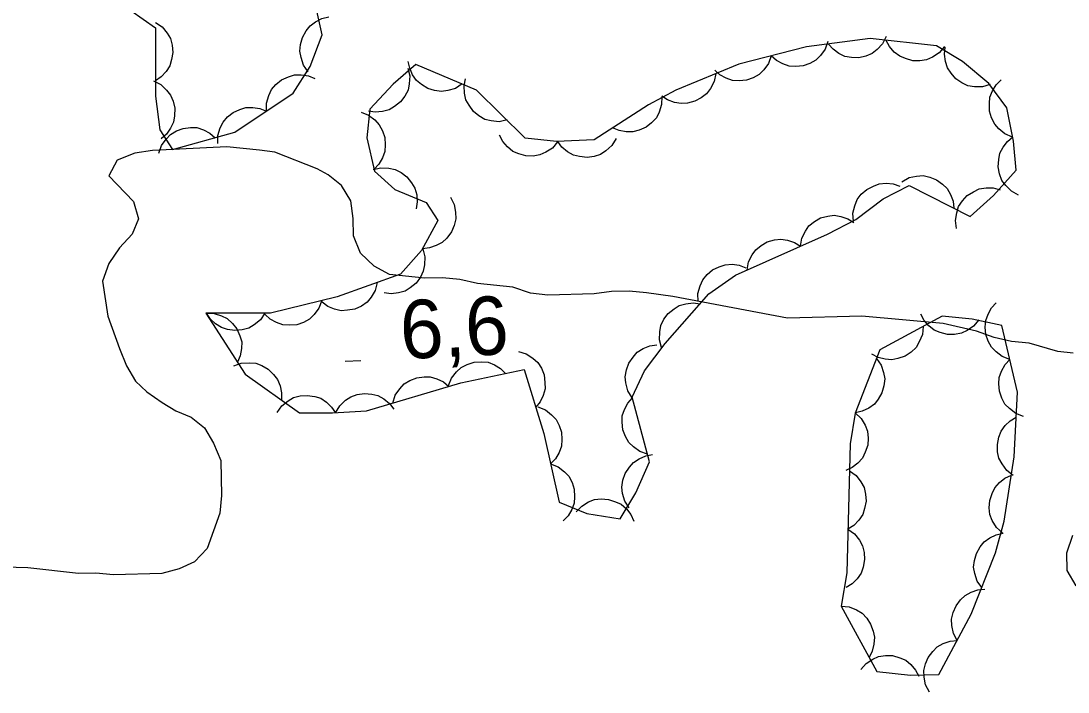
# Model space of a CAD drawing. Extents: x 336540 to 340074, y 5572036 to 5573747.
# Drawn here: x 337134.4 to 337188.2, y 5572878.8 to 5572913.2 of the extents above; entities that cross this region are included whole.
import ezdxf

# ---------------------------------------------------------------- set-up
doc = ezdxf.new("R2010")
doc.units = 0
for name, color, linetype in [('Niveau 2', 7, 'Continuous'), ('Niveau 3', 7, 'Continuous'), ('Niveau 44', 7, 'Continuous')]:
    doc.layers.add(name, color=color, linetype=linetype)

msp = doc.modelspace()

# ---------------------------------------------------------------- linework, layer by layer
at = {"layer": 'Niveau 2'}
for points in [[(337150.88, 5572904.79), (337150.19, 5572905.34), (337149.62, 5572905.66), (337147.46, 5572906.51), (337146.67, 5572906.61), (337144.98, 5572906.79), (337141.16, 5572906.59), (337140.26, 5572906.46), (337139.36, 5572906.1), (337138.93, 5572905.3), (337140.2, 5572903.98), (337140.45, 5572903.09), (337140.13, 5572902.29), (337139.47, 5572901.6), (337138.92, 5572900.8), (337138.6, 5572899.89), (337138.87, 5572898.09), (337139.47, 5572896.42), (337139.83, 5572895.53), (337140.3, 5572894.75), (337140.87, 5572894.2), (337141.67, 5572893.65), (337142.36, 5572893.22), (337143.15, 5572892.9), (337143.84, 5572892.35), (337144.31, 5572891.57), (337144.67, 5572890.68), (337144.71, 5572888.88), (337144.62, 5572887.98), (337143.98, 5572886.16), (337143.32, 5572885.47), (337142.54, 5572885.11), (337141.64, 5572884.87), (337139.17, 5572884.81), (337138.26, 5572884.9), (337137.36, 5572884.88), (337134.77, 5572885.16), (337130.6, 5572885.29)], [(337188.47, 5572896.19), (337187.68, 5572896.28), (337186.2, 5572896.7), (337185.3, 5572896.79), (337184.4, 5572896.99), (337183.49, 5572897.31), (337181.79, 5572897.72), (337177.61, 5572898.08), (337173.79, 5572897.99), (337167.9, 5572899.1), (337166.55, 5572899.29), (337165.65, 5572899.38), (337164.74, 5572899.36), (337163.85, 5572899.23), (337161.48, 5572899.17), (337160.58, 5572899.27), (337159.67, 5572899.58), (337157.87, 5572899.77), (337156.96, 5572899.97), (337156.06, 5572900.06), (337155.16, 5572900.04), (337153.35, 5572900.23), (337152.55, 5572900.66), (337151.86, 5572901.32), (337151.5, 5572902.21), (337151.48, 5572903.11), (337151.35, 5572904.01), (337150.88, 5572904.79)], [(337188.62, 5572884.25), (337188.16, 5572885.03), (337188.14, 5572885.93), (337188.45, 5572886.84)]]:
    msp.add_lwpolyline(points, dxfattribs=at)
at = {"layer": 'Niveau 3'}
msp.add_line((337151.07, 5572895.78), (337151.87, 5572895.82), dxfattribs=at)
at = {"layer": 'Niveau 44'}
for points in [[(337138.45, 5572914.43), (337140.05, 5572913.79), (337141.32, 5572912.9), (337141.32, 5572909.39), (337141.55, 5572907.66), (337142.2, 5572906.65), (337145.4, 5572907.53), (337148.4, 5572909.54), (337149.27, 5572910.9), (337149.88, 5572912.54), (337149.54, 5572914.07), (337148.69, 5572915.61), (337147.65, 5572916.8), (337144.62, 5572918.57), (337141.35, 5572917.79), (337139.97, 5572916.95), (337138.53, 5572915.98), (337138.45, 5572914.43)], [(337141.32, 5572913.17), (337141.67, 5572912.94), (337141.92, 5572912.62), (337142.09, 5572912.34), (337142.18, 5572912), (337142.22, 5572911.63), (337142.15, 5572911.26), (337142.06, 5572910.94), (337141.87, 5572910.65), (337141.62, 5572910.38), (337141.32, 5572910.17)], [(337149.17, 5572910.64), (337148.93, 5572910.98), (337148.8, 5572911.37), (337148.74, 5572911.69), (337148.77, 5572912.04), (337148.87, 5572912.4), (337149.06, 5572912.73), (337149.26, 5572912.99), (337149.54, 5572913.2), (337149.87, 5572913.37), (337150.22, 5572913.45)], [(337178.86, 5572912.45), (337178.67, 5572912.07), (337178.39, 5572911.78), (337178.14, 5572911.57), (337177.81, 5572911.44), (337177.45, 5572911.36), (337177.07, 5572911.37), (337176.74, 5572911.42), (337176.43, 5572911.57), (337176.13, 5572911.79), (337175.89, 5572912.06)], [(337143.91, 5572898.24), (337145.93, 5572895.11), (337148.72, 5572893.13), (337150.41, 5572893.12), (337152.16, 5572893.23), (337157.01, 5572894.66), (337160.26, 5572895.35), (337161.27, 5572892.07), (337162.06, 5572888.54), (337163.48, 5572887.95), (337165.2, 5572887.68), (337165.99, 5572889.01), (337166.7, 5572890.61), (337165.81, 5572893.93), (337166.45, 5572895.29), (337167.5, 5572896.69), (337169.75, 5572899.23), (337171.11, 5572900.19), (337175.84, 5572902.3), (337177.3, 5572903.05), (337178.7, 5572904.11), (337180.04, 5572904.8), (337183.17, 5572903.21), (337184.37, 5572904.28), (337185.53, 5572905.59), (337185.39, 5572907.07), (337185.05, 5572908.79), (337184.13, 5572910.04), (337182.78, 5572911.16), (337181.45, 5572911.97), (337178.04, 5572912.34), (337174.76, 5572911.91), (337171.29, 5572911.03), (337168.06, 5572909.69), (337166.64, 5572908.93), (337163.85, 5572907.15), (337161.92, 5572907.05), (337160.31, 5572907.23), (337157.82, 5572909.7), (337154.7, 5572911.01), (337153.53, 5572910), (337152.34, 5572908.71), (337152.18, 5572907.25), (337152.57, 5572905.54), (337153.61, 5572904.6), (337155.23, 5572903.92), (337155.82, 5572903), (337154.98, 5572901.46), (337153.91, 5572900.24), (337150.65, 5572899.08), (337147.23, 5572898.25), (337143.91, 5572898.24)], [(337175.86, 5572912.19), (337175.72, 5572911.8), (337175.48, 5572911.47), (337175.24, 5572911.23), (337174.94, 5572911.06), (337174.59, 5572910.94), (337174.21, 5572910.91), (337173.88, 5572910.92), (337173.55, 5572911.04), (337173.22, 5572911.21), (337172.95, 5572911.45)], [(337181.85, 5572911.93), (337181.58, 5572911.61), (337181.23, 5572911.39), (337180.93, 5572911.25), (337180.59, 5572911.19), (337180.22, 5572911.2), (337179.85, 5572911.31), (337179.55, 5572911.43), (337179.27, 5572911.65), (337179.03, 5572911.93), (337178.86, 5572912.25)], [(337184.2, 5572909.98), (337183.8, 5572909.87), (337183.39, 5572909.87), (337183.06, 5572909.92), (337182.74, 5572910.07), (337182.44, 5572910.28), (337182.19, 5572910.57), (337182, 5572910.84), (337181.9, 5572911.17), (337181.85, 5572911.54), (337181.89, 5572911.9)], [(337172.95, 5572911.45), (337172.81, 5572911.06), (337172.57, 5572910.73), (337172.34, 5572910.5), (337172.03, 5572910.33), (337171.68, 5572910.2), (337171.3, 5572910.17), (337170.97, 5572910.18), (337170.64, 5572910.3), (337170.31, 5572910.48), (337170.05, 5572910.71)], [(337154.29, 5572910.82), (337154.39, 5572910.42), (337154.36, 5572910.01), (337154.3, 5572909.69), (337154.13, 5572909.38), (337153.91, 5572909.09), (337153.6, 5572908.85), (337153.32, 5572908.68), (337152.98, 5572908.6), (337152.61, 5572908.57), (337152.26, 5572908.62)], [(337157.08, 5572910.01), (337156.73, 5572909.78), (337156.34, 5572909.67), (337156.01, 5572909.62), (337155.66, 5572909.67), (337155.31, 5572909.78), (337154.99, 5572909.99), (337154.73, 5572910.19), (337154.53, 5572910.48), (337154.38, 5572910.82), (337154.31, 5572911.17)], [(337147.02, 5572908.62), (337147.02, 5572909.03), (337147.14, 5572909.42), (337147.28, 5572909.72), (337147.51, 5572909.99), (337147.8, 5572910.22), (337148.15, 5572910.37), (337148.46, 5572910.48), (337148.81, 5572910.48), (337149.18, 5572910.42), (337149.51, 5572910.29)], [(337159.38, 5572908.16), (337158.97, 5572908.07), (337158.56, 5572908.12), (337158.24, 5572908.19), (337157.94, 5572908.37), (337157.65, 5572908.6), (337157.43, 5572908.92), (337157.27, 5572909.2), (337157.2, 5572909.54), (337157.18, 5572909.91), (337157.25, 5572910.27)], [(337170.1, 5572910.54), (337170.02, 5572910.13), (337169.83, 5572909.77), (337169.63, 5572909.5), (337169.35, 5572909.29), (337169.02, 5572909.12), (337168.65, 5572909.03), (337168.33, 5572909), (337167.98, 5572909.06), (337167.63, 5572909.19), (337167.33, 5572909.39)], [(337141.22, 5572910.17), (337141.59, 5572909.98), (337141.89, 5572909.7), (337142.09, 5572909.44), (337142.23, 5572909.12), (337142.31, 5572908.76), (337142.29, 5572908.38), (337142.25, 5572908.05), (337142.09, 5572907.74), (337141.88, 5572907.43), (337141.61, 5572907.19)], [(337185.35, 5572907.28), (337184.96, 5572907.45), (337184.65, 5572907.71), (337184.43, 5572907.95), (337184.27, 5572908.27), (337184.17, 5572908.62), (337184.16, 5572909), (337184.18, 5572909.33), (337184.32, 5572909.66), (337184.51, 5572909.97), (337184.77, 5572910.23)], [(337167.33, 5572909.37), (337167.32, 5572908.96), (337167.19, 5572908.57), (337167.05, 5572908.27), (337166.81, 5572908.01), (337166.52, 5572907.79), (337166.16, 5572907.64), (337165.85, 5572907.55), (337165.5, 5572907.55), (337165.14, 5572907.62), (337164.8, 5572907.76)], [(337144.53, 5572906.95), (337144.53, 5572907.36), (337144.65, 5572907.75), (337144.79, 5572908.05), (337145.02, 5572908.32), (337145.31, 5572908.55), (337145.66, 5572908.7), (337145.97, 5572908.81), (337146.32, 5572908.81), (337146.69, 5572908.75), (337147.02, 5572908.62)], [(337151.88, 5572908.56), (337152.27, 5572908.41), (337152.59, 5572908.16), (337152.82, 5572907.92), (337152.98, 5572907.61), (337153.1, 5572907.26), (337153.12, 5572906.88), (337153.1, 5572906.55), (337152.98, 5572906.22), (337152.79, 5572905.9), (337152.55, 5572905.64)], [(337141.5, 5572906.46), (337141.63, 5572906.85), (337141.87, 5572907.18), (337142.09, 5572907.42), (337142.4, 5572907.6), (337142.74, 5572907.73), (337143.12, 5572907.77), (337143.45, 5572907.77), (337143.79, 5572907.66), (337144.11, 5572907.49), (337144.39, 5572907.25)], [(337161.98, 5572907.04), (337161.71, 5572906.72), (337161.37, 5572906.51), (337161.07, 5572906.37), (337160.72, 5572906.31), (337160.35, 5572906.32), (337159.99, 5572906.43), (337159.68, 5572906.55), (337159.41, 5572906.78), (337159.17, 5572907.06), (337159, 5572907.38)], [(337164.98, 5572907.21), (337164.77, 5572906.85), (337164.46, 5572906.58), (337164.19, 5572906.39), (337163.86, 5572906.29), (337163.49, 5572906.23), (337163.11, 5572906.28), (337162.79, 5572906.35), (337162.49, 5572906.53), (337162.2, 5572906.77), (337161.99, 5572907.05)], [(337185.65, 5572904.3), (337185.29, 5572904.5), (337185, 5572904.79), (337184.8, 5572905.06), (337184.68, 5572905.39), (337184.61, 5572905.75), (337184.64, 5572906.13), (337184.7, 5572906.45), (337184.87, 5572906.76), (337185.09, 5572907.06), (337185.37, 5572907.29)], [(337152.5, 5572905.61), (337152.9, 5572905.71), (337153.31, 5572905.68), (337153.63, 5572905.62), (337153.94, 5572905.46), (337154.24, 5572905.24), (337154.48, 5572904.94), (337154.65, 5572904.66), (337154.74, 5572904.32), (337154.77, 5572903.95), (337154.72, 5572903.6)], [(337177.17, 5572902.95), (337177.15, 5572903.37), (337177.25, 5572903.76), (337177.37, 5572904.07), (337177.58, 5572904.35), (337177.86, 5572904.6), (337178.2, 5572904.77), (337178.5, 5572904.89), (337178.85, 5572904.91), (337179.22, 5572904.88), (337179.56, 5572904.76)], [(337179.66, 5572904.99), (337180.03, 5572905.2), (337180.42, 5572905.28), (337180.75, 5572905.31), (337181.1, 5572905.23), (337181.44, 5572905.09), (337181.75, 5572904.87), (337181.99, 5572904.65), (337182.16, 5572904.34), (337182.29, 5572903.99), (337182.33, 5572903.63)], [(337182.47, 5572902.59), (337182.42, 5572903), (337182.48, 5572903.4), (337182.58, 5572903.72), (337182.77, 5572904.01), (337183.02, 5572904.28), (337183.35, 5572904.48), (337183.64, 5572904.63), (337183.99, 5572904.68), (337184.36, 5572904.67), (337184.71, 5572904.58)], [(337156.47, 5572904.19), (337156.66, 5572903.82), (337156.73, 5572903.42), (337156.75, 5572903.09), (337156.66, 5572902.74), (337156.52, 5572902.41), (337156.28, 5572902.1), (337156.05, 5572901.87), (337155.74, 5572901.71), (337155.39, 5572901.59), (337155.03, 5572901.55)], [(337174.45, 5572901.68), (337174.52, 5572902.09), (337174.71, 5572902.45), (337174.89, 5572902.73), (337175.17, 5572902.95), (337175.49, 5572903.13), (337175.86, 5572903.22), (337176.19, 5572903.27), (337176.53, 5572903.21), (337176.88, 5572903.09), (337177.19, 5572902.9)], [(337171.71, 5572900.46), (337171.78, 5572900.87), (337171.97, 5572901.23), (337172.16, 5572901.5), (337172.43, 5572901.72), (337172.75, 5572901.9), (337173.12, 5572902), (337173.45, 5572902.05), (337173.79, 5572901.99), (337174.14, 5572901.87), (337174.45, 5572901.68)], [(337155.05, 5572901.54), (337155.16, 5572901.14), (337155.14, 5572900.73), (337155.08, 5572900.4), (337154.93, 5572900.09), (337154.71, 5572899.79), (337154.41, 5572899.55), (337154.14, 5572899.37), (337153.8, 5572899.28), (337153.43, 5572899.24), (337153.07, 5572899.28)], [(337169.2, 5572898.84), (337169.19, 5572899.26), (337169.3, 5572899.65), (337169.43, 5572899.95), (337169.66, 5572900.22), (337169.94, 5572900.46), (337170.28, 5572900.62), (337170.59, 5572900.73), (337170.94, 5572900.75), (337171.31, 5572900.7), (337171.65, 5572900.57)], [(337152.71, 5572899.81), (337152.61, 5572899.41), (337152.4, 5572899.06), (337152.19, 5572898.81), (337151.9, 5572898.61), (337151.56, 5572898.45), (337151.18, 5572898.39), (337150.86, 5572898.36), (337150.52, 5572898.45), (337150.18, 5572898.59), (337149.89, 5572898.81)], [(337149.86, 5572898.89), (337149.72, 5572898.5), (337149.47, 5572898.17), (337149.24, 5572897.94), (337148.93, 5572897.77), (337148.58, 5572897.65), (337148.19, 5572897.63), (337147.87, 5572897.64), (337147.54, 5572897.76), (337147.21, 5572897.94), (337146.95, 5572898.18)], [(337167.31, 5572896.48), (337167.21, 5572896.88), (337167.23, 5572897.29), (337167.28, 5572897.61), (337167.44, 5572897.93), (337167.66, 5572898.22), (337167.96, 5572898.46), (337168.23, 5572898.64), (337168.57, 5572898.73), (337168.94, 5572898.77), (337169.3, 5572898.72)], [(337185.21, 5572895.86), (337184.82, 5572896.01), (337184.5, 5572896.26), (337184.26, 5572896.49), (337184.1, 5572896.8), (337183.98, 5572897.15), (337183.95, 5572897.53), (337183.97, 5572897.86), (337184.09, 5572898.19), (337184.27, 5572898.51), (337184.51, 5572898.78)], [(337143.91, 5572898.24), (337144.33, 5572898.23), (337144.71, 5572898.1), (337145.01, 5572897.96), (337145.27, 5572897.72), (337145.5, 5572897.43), (337145.65, 5572897.08), (337145.75, 5572896.77), (337145.74, 5572896.42), (337145.68, 5572896.05), (337145.54, 5572895.72)], [(337146.94, 5572898.25), (337146.71, 5572897.9), (337146.39, 5572897.65), (337146.11, 5572897.47), (337145.77, 5572897.38), (337145.4, 5572897.35), (337145.02, 5572897.41), (337144.71, 5572897.5), (337144.41, 5572897.69), (337144.14, 5572897.94), (337143.94, 5572898.24)], [(337176.54, 5572883.2), (337178.37, 5572879.85), (337180.11, 5572879.65), (337181.56, 5572879.69), (337183.23, 5572882.78), (337184.47, 5572885.94), (337184.92, 5572887.57), (337185.43, 5572890.86), (337185.61, 5572894.19), (337184.79, 5572897.61), (337183.27, 5572897.93), (337181.73, 5572898.08), (337178.53, 5572896.36), (337177.27, 5572893.1), (337177.01, 5572891.53), (337176.83, 5572884.91), (337176.54, 5572883.2)], [(337183.62, 5572897.9), (337183.35, 5572897.57), (337183.01, 5572897.35), (337182.72, 5572897.21), (337182.37, 5572897.15), (337182, 5572897.15), (337181.63, 5572897.25), (337181.33, 5572897.37), (337181.05, 5572897.59), (337180.81, 5572897.87), (337180.63, 5572898.19)], [(337180.76, 5572897.56), (337180.72, 5572897.14), (337180.56, 5572896.77), (337180.39, 5572896.48), (337180.14, 5572896.24), (337179.83, 5572896.04), (337179.46, 5572895.92), (337179.15, 5572895.85), (337178.8, 5572895.88), (337178.44, 5572895.97), (337178.12, 5572896.14)], [(337159.97, 5572896.28), (337160.37, 5572896.15), (337160.71, 5572895.93), (337160.96, 5572895.71), (337161.15, 5572895.41), (337161.28, 5572895.07), (337161.33, 5572894.69), (337161.34, 5572894.36), (337161.24, 5572894.02), (337161.08, 5572893.69), (337160.86, 5572893.41)], [(337165.8, 5572893.9), (337165.58, 5572894.26), (337165.49, 5572894.66), (337165.45, 5572894.98), (337165.51, 5572895.33), (337165.64, 5572895.68), (337165.86, 5572895.99), (337166.07, 5572896.24), (337166.37, 5572896.42), (337166.72, 5572896.56), (337167.07, 5572896.62)], [(337156.38, 5572894.53), (337156.53, 5572894.91), (337156.79, 5572895.23), (337157.03, 5572895.46), (337157.34, 5572895.61), (337157.7, 5572895.72), (337158.08, 5572895.74), (337158.41, 5572895.72), (337158.73, 5572895.59), (337159.05, 5572895.4), (337159.31, 5572895.15)], [(337178.36, 5572895.92), (337178.6, 5572895.58), (337178.72, 5572895.19), (337178.78, 5572894.87), (337178.74, 5572894.52), (337178.64, 5572894.16), (337178.45, 5572893.83), (337178.25, 5572893.57), (337177.96, 5572893.37), (337177.63, 5572893.21), (337177.28, 5572893.13)], [(337185.91, 5572892.94), (337185.52, 5572893.09), (337185.2, 5572893.34), (337184.96, 5572893.57), (337184.8, 5572893.88), (337184.68, 5572894.23), (337184.65, 5572894.62), (337184.66, 5572894.94), (337184.78, 5572895.27), (337184.97, 5572895.6), (337185.21, 5572895.86)], [(337145.34, 5572895.53), (337145.73, 5572895.68), (337146.14, 5572895.7), (337146.47, 5572895.68), (337146.79, 5572895.56), (337147.11, 5572895.37), (337147.38, 5572895.1), (337147.59, 5572894.84), (337147.72, 5572894.52), (337147.79, 5572894.15), (337147.79, 5572893.79)], [(337153.51, 5572893.63), (337153.64, 5572894.03), (337153.87, 5572894.36), (337154.09, 5572894.61), (337154.39, 5572894.79), (337154.74, 5572894.92), (337155.12, 5572894.97), (337155.44, 5572894.97), (337155.78, 5572894.87), (337156.11, 5572894.71), (337156.39, 5572894.48)], [(337147.57, 5572893.14), (337147.81, 5572893.48), (337148.13, 5572893.74), (337148.41, 5572893.91), (337148.75, 5572893.99), (337149.12, 5572894.02), (337149.5, 5572893.96), (337149.81, 5572893.87), (337150.1, 5572893.67), (337150.37, 5572893.42), (337150.57, 5572893.12)], [(337150.57, 5572893.13), (337150.79, 5572893.49), (337151.08, 5572893.77), (337151.36, 5572893.95), (337151.69, 5572894.07), (337152.05, 5572894.12), (337152.44, 5572894.08), (337152.75, 5572894.01), (337153.06, 5572893.84), (337153.35, 5572893.6), (337153.57, 5572893.32)], [(337166.59, 5572891), (337166.2, 5572891.14), (337165.87, 5572891.38), (337165.63, 5572891.61), (337165.46, 5572891.91), (337165.33, 5572892.26), (337165.29, 5572892.64), (337165.3, 5572892.97), (337165.41, 5572893.3), (337165.58, 5572893.63), (337165.82, 5572893.9)], [(337160.96, 5572893.44), (337161.35, 5572893.28), (337161.67, 5572893.03), (337161.9, 5572892.79), (337162.06, 5572892.48), (337162.17, 5572892.13), (337162.19, 5572891.75), (337162.18, 5572891.42), (337162.05, 5572891.09), (337161.87, 5572890.77), (337161.62, 5572890.51)], [(337177.27, 5572893.13), (337177.58, 5572892.84), (337177.78, 5572892.49), (337177.9, 5572892.18), (337177.94, 5572891.83), (337177.91, 5572891.46), (337177.78, 5572891.1), (337177.64, 5572890.8), (337177.4, 5572890.54), (337177.11, 5572890.32), (337176.78, 5572890.17)], [(337185.38, 5572889.91), (337185.05, 5572890.17), (337184.81, 5572890.5), (337184.65, 5572890.79), (337184.58, 5572891.13), (337184.57, 5572891.5), (337184.65, 5572891.87), (337184.76, 5572892.18), (337184.97, 5572892.47), (337185.23, 5572892.72), (337185.54, 5572892.91)], [(337165.65, 5572888.24), (337165.43, 5572888.59), (337165.32, 5572888.99), (337165.28, 5572889.31), (337165.33, 5572889.66), (337165.45, 5572890.01), (337165.67, 5572890.33), (337165.87, 5572890.58), (337166.17, 5572890.77), (337166.51, 5572890.92), (337166.86, 5572890.98)], [(337161.62, 5572890.51), (337162.01, 5572890.36), (337162.33, 5572890.1), (337162.56, 5572889.87), (337162.72, 5572889.55), (337162.83, 5572889.2), (337162.85, 5572888.82), (337162.83, 5572888.49), (337162.71, 5572888.16), (337162.52, 5572887.84), (337162.27, 5572887.58)], [(337176.97, 5572890.15), (337177.31, 5572889.91), (337177.56, 5572889.58), (337177.72, 5572889.3), (337177.8, 5572888.95), (337177.83, 5572888.59), (337177.75, 5572888.21), (337177.66, 5572887.9), (337177.45, 5572887.61), (337177.19, 5572887.34), (337176.89, 5572887.15)], [(337184.83, 5572886.96), (337184.52, 5572887.24), (337184.31, 5572887.6), (337184.19, 5572887.9), (337184.15, 5572888.25), (337184.18, 5572888.62), (337184.3, 5572888.98), (337184.43, 5572889.28), (337184.67, 5572889.54), (337184.96, 5572889.77), (337185.29, 5572889.92)], [(337162.93, 5572888.04), (337163.22, 5572888.34), (337163.57, 5572888.55), (337163.87, 5572888.67), (337164.22, 5572888.71), (337164.59, 5572888.68), (337164.95, 5572888.56), (337165.25, 5572888.43), (337165.51, 5572888.19), (337165.74, 5572887.9), (337165.89, 5572887.57)], [(337176.89, 5572887.15), (337177.23, 5572886.91), (337177.48, 5572886.58), (337177.64, 5572886.3), (337177.72, 5572885.95), (337177.74, 5572885.59), (337177.67, 5572885.21), (337177.57, 5572884.9), (337177.37, 5572884.61), (337177.11, 5572884.34), (337176.81, 5572884.15)], [(337183.77, 5572884.15), (337183.53, 5572884.49), (337183.41, 5572884.88), (337183.35, 5572885.2), (337183.39, 5572885.55), (337183.49, 5572885.91), (337183.69, 5572886.24), (337183.89, 5572886.5), (337184.18, 5572886.7), (337184.51, 5572886.86), (337184.86, 5572886.94)], [(337182.5, 5572881.43), (337182.31, 5572881.8), (337182.23, 5572882.2), (337182.22, 5572882.53), (337182.3, 5572882.87), (337182.45, 5572883.21), (337182.68, 5572883.52), (337182.91, 5572883.75), (337183.22, 5572883.92), (337183.57, 5572884.04), (337183.93, 5572884.07)], [(337176.54, 5572883.2), (337176.96, 5572883.16), (337177.33, 5572883.01), (337177.62, 5572882.84), (337177.86, 5572882.59), (337178.06, 5572882.28), (337178.19, 5572881.92), (337178.26, 5572881.6), (337178.23, 5572881.25), (337178.14, 5572880.89), (337177.98, 5572880.57)], [(337181.08, 5572878.79), (337180.88, 5572879.16), (337180.81, 5572879.56), (337180.79, 5572879.89), (337180.87, 5572880.24), (337181.02, 5572880.57), (337181.26, 5572880.88), (337181.48, 5572881.11), (337181.79, 5572881.28), (337182.14, 5572881.4), (337182.5, 5572881.43)], [(337177.56, 5572879.94), (337177.83, 5572880.26), (337178.17, 5572880.48), (337178.47, 5572880.62), (337178.82, 5572880.67), (337179.19, 5572880.66), (337179.56, 5572880.55), (337179.86, 5572880.43), (337180.13, 5572880.2), (337180.37, 5572879.92), (337180.54, 5572879.6)]]:
    msp.add_lwpolyline(points, dxfattribs=at)

# ---------------------------------------------------------------- texts
at = {"layer": 'Niveau 3'}
msp.add_text('6,6    ', height=3, rotation=2.7712, dxfattribs=at).set_placement((337153.95, 5572895.88))

doc.saveas('drawing.dxf')
